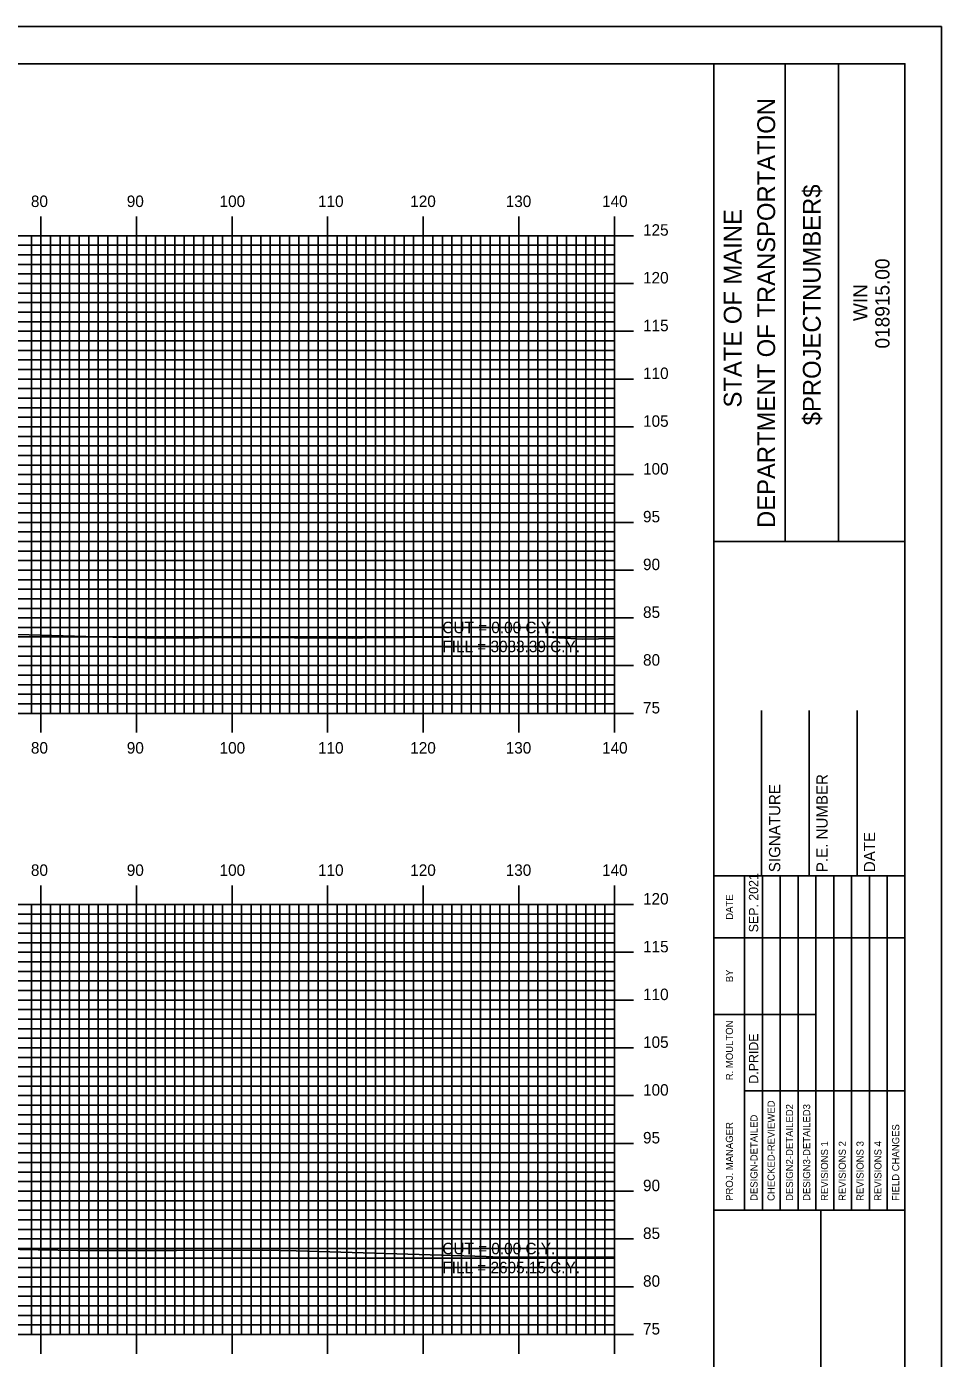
# Model space of a CAD drawing. Extents: x 855690 to 856034, y 364366 to 364586.
# Drawn here: x 855934.8 to 856030.5, y 364446.3 to 364585.7 of the extents above; entities that cross this region are included whole.
import ezdxf

# ---------------------------------------------------------------- set-up
doc = ezdxf.new("R2010")
doc.units = 0
for name, color, linetype in [('BORDER', 7, 'Continuous'), ('D_Text_Standard', 7, 'Continuous'), ('H_V ANNOTATION', 7, 'Continuous'), ('MAJOR', 7, 'Continuous'), ('MINOR', 7, 'Continuous'), ('PLOT BOUNDARY', 7, 'Continuous'), ('S_Roadway_Centerline', 7, 'Continuous')]:
    doc.layers.add(name, color=color, linetype=linetype)

msp = doc.modelspace()

# ---------------------------------------------------------------- linework, layer by layer
at = {"layer": 'BORDER'}
for p, q in [((856006.68, 364371.79), (856006.68, 364581.79)), ((856014.14, 364531.78), (856014.14, 364581.78)), ((856019.73, 364531.78), (856019.73, 364581.78)), ((856006.68, 364531.78), (856026.68, 364531.78)), ((856011.68, 364496.79), (856011.68, 364514.09)), ((856016.68, 364496.79), (856016.68, 364514.09)), ((856021.68, 364496.79), (856021.68, 364514.09)), ((856006.68, 364496.79), (856026.68, 364496.79)), ((856006.68, 364461.79), (856026.68, 364461.79)), ((856017.87, 364391.79), (856017.87, 364461.79))]:
    msp.add_line(p, q, dxfattribs=at)
msp.add_lwpolyline([(855706.68, 364371.79), (856026.68, 364371.79), (856026.68, 364581.79), (855706.68, 364581.79)], close=True, dxfattribs=at)
for points in [[(856009.91, 364490.29), (856009.91, 364496.79)], [(856011.78, 364461.8), (856011.78, 364496.79)], [(856013.64, 364496.79), (856013.64, 364461.8)], [(856015.5, 364461.8), (856015.5, 364496.79)], [(856017.37, 364461.8), (856017.37, 364496.79)], [(856019.23, 364461.8), (856019.23, 364496.79)], [(856021.09, 364461.8), (856021.09, 364496.79)], [(856022.96, 364461.8), (856022.96, 364496.79)], [(856024.82, 364461.8), (856024.82, 364496.79)], [(856009.91, 364461.8), (856009.91, 364495.38)], [(856006.68, 364490.29), (856026.68, 364490.29)], [(856006.68, 364482.29), (856009.91, 364482.29)], [(856009.91, 364482.29), (856017.37, 364482.29)], [(856009.91, 364474.29), (856026.68, 364474.29)]]:
    msp.add_lwpolyline(points, dxfattribs=at)
at = {"layer": 'MAJOR'}
for p, q in [((855936.28, 364565.79), (855936.28, 364563.79)), ((855946.28, 364565.79), (855946.28, 364563.79)), ((855956.28, 364565.79), (855956.28, 364563.79)), ((855966.28, 364565.79), (855966.28, 364563.79)), ((855976.28, 364565.79), (855976.28, 364563.79)), ((855986.28, 364565.79), (855986.28, 364563.79)), ((855996.28, 364565.79), (855996.28, 364563.79)), ((855716.28, 364563.79), (855996.28, 364563.79)), ((855716.28, 364563.79), (855996.28, 364563.79)), ((855936.28, 364513.79), (855936.28, 364563.79)), ((855946.28, 364513.79), (855946.28, 364563.79)), ((855956.28, 364513.79), (855956.28, 364563.79)), ((855966.28, 364513.79), (855966.28, 364563.79)), ((855976.28, 364513.79), (855976.28, 364563.79)), ((855986.28, 364513.79), (855986.28, 364563.79)), ((855998.29, 364563.79), (855994.28, 364563.79)), ((855996.28, 364513.79), (855996.28, 364563.79)), ((855996.28, 364513.79), (855996.28, 364563.79)), ((855716.28, 364558.79), (855996.28, 364558.79)), ((855998.29, 364558.79), (855994.28, 364558.79)), ((855716.28, 364553.79), (855996.28, 364553.79)), ((855998.29, 364553.79), (855994.28, 364553.79)), ((855716.28, 364548.79), (855996.28, 364548.79)), ((855998.29, 364548.79), (855994.28, 364548.79)), ((855716.28, 364543.79), (855996.28, 364543.79)), ((855998.29, 364543.79), (855994.28, 364543.79)), ((855716.28, 364538.79), (855996.28, 364538.79)), ((855998.29, 364538.79), (855994.28, 364538.79)), ((855716.28, 364533.79), (855996.28, 364533.79)), ((855998.29, 364533.79), (855994.28, 364533.79)), ((855716.28, 364528.79), (855996.28, 364528.79)), ((855998.29, 364528.79), (855994.28, 364528.79)), ((855716.28, 364523.79), (855996.28, 364523.79)), ((855998.29, 364523.79), (855994.28, 364523.79)), ((855716.28, 364518.79), (855996.28, 364518.79)), ((855998.29, 364518.79), (855994.28, 364518.79)), ((855716.28, 364513.79), (855996.28, 364513.79)), ((855716.28, 364513.79), (855996.28, 364513.79)), ((855936.28, 364511.78), (855936.28, 364513.79)), ((855946.28, 364511.78), (855946.28, 364513.79)), ((855956.28, 364511.78), (855956.28, 364513.79)), ((855966.28, 364511.78), (855966.28, 364513.79)), ((855976.28, 364511.78), (855976.28, 364513.79)), ((855986.28, 364511.78), (855986.28, 364513.79)), ((855998.29, 364513.79), (855994.28, 364513.79)), ((855996.28, 364511.78), (855996.28, 364513.79)), ((855936.28, 364495.79), (855936.28, 364493.79)), ((855946.28, 364495.79), (855946.28, 364493.79)), ((855956.28, 364495.79), (855956.28, 364493.79)), ((855966.28, 364495.79), (855966.28, 364493.79)), ((855976.28, 364495.79), (855976.28, 364493.79)), ((855986.28, 364495.79), (855986.28, 364493.79)), ((855996.28, 364495.79), (855996.28, 364493.79)), ((855716.28, 364493.79), (855996.28, 364493.79)), ((855716.28, 364493.79), (855996.28, 364493.79)), ((855936.28, 364448.79), (855936.28, 364493.79)), ((855946.28, 364448.79), (855946.28, 364493.79)), ((855956.28, 364448.79), (855956.28, 364493.79)), ((855966.28, 364448.79), (855966.28, 364493.79)), ((855976.28, 364448.79), (855976.28, 364493.79)), ((855986.28, 364448.79), (855986.28, 364493.79)), ((855998.29, 364493.79), (855994.28, 364493.79)), ((855996.28, 364448.79), (855996.28, 364493.79)), ((855996.28, 364448.79), (855996.28, 364493.79)), ((855716.28, 364488.79), (855996.28, 364488.79)), ((855998.29, 364488.79), (855994.28, 364488.79)), ((855716.28, 364483.79), (855996.28, 364483.79)), ((855998.29, 364483.79), (855994.28, 364483.79)), ((855716.28, 364478.79), (855996.28, 364478.79)), ((855998.29, 364478.79), (855994.28, 364478.79)), ((855716.28, 364473.79), (855996.28, 364473.79)), ((855998.29, 364473.79), (855994.28, 364473.79)), ((855716.28, 364468.79), (855996.28, 364468.79)), ((855998.29, 364468.79), (855994.28, 364468.79)), ((855716.28, 364463.79), (855996.28, 364463.79)), ((855998.29, 364463.79), (855994.28, 364463.79)), ((855716.28, 364458.79), (855996.28, 364458.79)), ((855998.29, 364458.79), (855994.28, 364458.79)), ((855716.28, 364453.79), (855996.28, 364453.79)), ((855998.29, 364453.79), (855994.28, 364453.79)), ((855716.28, 364448.79), (855996.28, 364448.79)), ((855716.28, 364448.79), (855996.28, 364448.79)), ((855936.28, 364446.78), (855936.28, 364448.79)), ((855946.28, 364446.78), (855946.28, 364448.79)), ((855956.28, 364446.78), (855956.28, 364448.79)), ((855966.28, 364446.78), (855966.28, 364448.79)), ((855976.28, 364446.78), (855976.28, 364448.79)), ((855986.28, 364446.78), (855986.28, 364448.79)), ((855998.29, 364448.79), (855994.28, 364448.79)), ((855996.28, 364446.78), (855996.28, 364448.79))]:
    msp.add_line(p, q, dxfattribs=at)
at = {"layer": 'MINOR'}
for p, q in [((855716.28, 364562.79), (855996.28, 364562.79)), ((855935.28, 364513.79), (855935.28, 364563.79)), ((855937.28, 364513.79), (855937.28, 364563.79)), ((855938.28, 364513.79), (855938.28, 364563.79)), ((855939.28, 364513.79), (855939.28, 364563.79)), ((855940.28, 364513.79), (855940.28, 364563.79)), ((855941.28, 364513.79), (855941.28, 364563.79)), ((855942.28, 364513.79), (855942.28, 364563.79)), ((855943.28, 364513.79), (855943.28, 364563.79)), ((855944.28, 364513.79), (855944.28, 364563.79)), ((855945.28, 364513.79), (855945.28, 364563.79)), ((855947.28, 364513.79), (855947.28, 364563.79)), ((855948.28, 364513.79), (855948.28, 364563.79)), ((855949.28, 364513.79), (855949.28, 364563.79)), ((855950.28, 364513.79), (855950.28, 364563.79)), ((855951.28, 364513.79), (855951.28, 364563.79)), ((855952.28, 364513.79), (855952.28, 364563.79)), ((855953.28, 364513.79), (855953.28, 364563.79)), ((855954.28, 364513.79), (855954.28, 364563.79)), ((855955.28, 364513.79), (855955.28, 364563.79)), ((855957.28, 364513.79), (855957.28, 364563.79)), ((855958.28, 364513.79), (855958.28, 364563.79)), ((855959.28, 364513.79), (855959.28, 364563.79)), ((855960.28, 364513.79), (855960.28, 364563.79)), ((855961.28, 364513.79), (855961.28, 364563.79)), ((855962.28, 364513.79), (855962.28, 364563.79)), ((855963.28, 364513.79), (855963.28, 364563.79)), ((855964.28, 364513.79), (855964.28, 364563.79)), ((855965.28, 364513.79), (855965.28, 364563.79)), ((855967.28, 364513.79), (855967.28, 364563.79)), ((855968.28, 364513.79), (855968.28, 364563.79)), ((855969.28, 364513.79), (855969.28, 364563.79)), ((855970.28, 364513.79), (855970.28, 364563.79)), ((855971.28, 364513.79), (855971.28, 364563.79)), ((855972.28, 364513.79), (855972.28, 364563.79)), ((855973.28, 364513.79), (855973.28, 364563.79)), ((855974.28, 364513.79), (855974.28, 364563.79)), ((855975.28, 364513.79), (855975.28, 364563.79)), ((855977.28, 364513.79), (855977.28, 364563.79)), ((855978.28, 364513.79), (855978.28, 364563.79)), ((855979.28, 364513.79), (855979.28, 364563.79)), ((855980.28, 364513.79), (855980.28, 364563.79)), ((855981.28, 364513.79), (855981.28, 364563.79)), ((855982.28, 364513.79), (855982.28, 364563.79)), ((855983.28, 364513.79), (855983.28, 364563.79)), ((855984.28, 364513.79), (855984.28, 364563.79)), ((855985.28, 364513.79), (855985.28, 364563.79)), ((855987.28, 364513.79), (855987.28, 364563.79)), ((855988.28, 364513.79), (855988.28, 364563.79)), ((855989.28, 364513.79), (855989.28, 364563.79)), ((855990.28, 364513.79), (855990.28, 364563.79)), ((855991.28, 364513.79), (855991.28, 364563.79)), ((855992.28, 364513.79), (855992.28, 364563.79)), ((855993.28, 364513.79), (855993.28, 364563.79)), ((855994.28, 364513.79), (855994.28, 364563.79)), ((855996.28, 364562.79), (855994.28, 364562.79)), ((855995.28, 364513.79), (855995.28, 364563.79)), ((855716.28, 364561.79), (855996.28, 364561.79)), ((855996.28, 364561.79), (855994.28, 364561.79)), ((855716.28, 364560.79), (855996.28, 364560.79)), ((855996.28, 364560.79), (855994.28, 364560.79)), ((855716.28, 364559.79), (855996.28, 364559.79)), ((855996.28, 364559.79), (855994.28, 364559.79)), ((855716.28, 364557.79), (855996.28, 364557.79)), ((855996.28, 364557.79), (855994.28, 364557.79)), ((855716.28, 364556.79), (855996.28, 364556.79)), ((855716.28, 364555.79), (855996.28, 364555.79)), ((855996.28, 364556.79), (855994.28, 364556.79)), ((855996.28, 364555.79), (855994.28, 364555.79)), ((855716.28, 364554.79), (855996.28, 364554.79)), ((855996.28, 364554.79), (855994.28, 364554.79)), ((855716.28, 364552.79), (855996.28, 364552.79)), ((855716.28, 364551.79), (855996.28, 364551.79)), ((855996.28, 364552.79), (855994.28, 364552.79)), ((855996.28, 364551.79), (855994.28, 364551.79)), ((855716.28, 364550.79), (855996.28, 364550.79)), ((855996.28, 364550.79), (855994.28, 364550.79)), ((855716.28, 364549.79), (855996.28, 364549.79)), ((855996.28, 364549.79), (855994.28, 364549.79)), ((855716.28, 364547.79), (855996.28, 364547.79)), ((855996.28, 364547.79), (855994.28, 364547.79)), ((855716.28, 364546.79), (855996.28, 364546.79)), ((855996.28, 364546.79), (855994.28, 364546.79)), ((855716.28, 364545.79), (855996.28, 364545.79)), ((855716.28, 364544.79), (855996.28, 364544.79)), ((855996.28, 364545.79), (855994.28, 364545.79)), ((855996.28, 364544.79), (855994.28, 364544.79)), ((855716.28, 364542.79), (855996.28, 364542.79)), ((855716.28, 364541.79), (855996.28, 364541.79)), ((855996.28, 364542.79), (855994.28, 364542.79)), ((855996.28, 364541.79), (855994.28, 364541.79)), ((855716.28, 364540.79), (855996.28, 364540.79)), ((855996.28, 364540.79), (855994.28, 364540.79)), ((855716.28, 364539.79), (855996.28, 364539.79)), ((855996.28, 364539.79), (855994.28, 364539.79)), ((855716.28, 364537.79), (855996.28, 364537.79)), ((855996.28, 364537.79), (855994.28, 364537.79)), ((855716.28, 364536.79), (855996.28, 364536.79)), ((855996.28, 364536.79), (855994.28, 364536.79)), ((855716.28, 364535.79), (855996.28, 364535.79)), ((855716.28, 364534.79), (855996.28, 364534.79)), ((855996.28, 364535.79), (855994.28, 364535.79)), ((855996.28, 364534.79), (855994.28, 364534.79)), ((855716.28, 364532.79), (855996.28, 364532.79)), ((855996.28, 364532.79), (855994.28, 364532.79)), ((855716.28, 364531.79), (855996.28, 364531.79)), ((855716.28, 364530.79), (855996.28, 364530.79)), ((855996.28, 364531.79), (855994.28, 364531.79)), ((855996.28, 364530.79), (855994.28, 364530.79)), ((855716.28, 364529.79), (855996.28, 364529.79)), ((855996.28, 364529.79), (855994.28, 364529.79)), ((855716.28, 364527.79), (855996.28, 364527.79)), ((855996.28, 364527.79), (855994.28, 364527.79)), ((855716.28, 364526.79), (855996.28, 364526.79)), ((855996.28, 364526.79), (855994.28, 364526.79)), ((855716.28, 364525.79), (855996.28, 364525.79)), ((855996.28, 364525.79), (855994.28, 364525.79)), ((855716.28, 364524.79), (855996.28, 364524.79)), ((855996.28, 364524.79), (855994.28, 364524.79)), ((855716.28, 364522.79), (855996.28, 364522.79)), ((855996.28, 364522.79), (855994.28, 364522.79)), ((855716.28, 364521.79), (855996.28, 364521.79)), ((855716.28, 364520.79), (855996.28, 364520.79)), ((855996.28, 364521.79), (855994.28, 364521.79)), ((855996.28, 364520.79), (855994.28, 364520.79)), ((855716.28, 364519.79), (855996.28, 364519.79)), ((855996.28, 364519.79), (855994.28, 364519.79)), ((855716.28, 364517.79), (855996.28, 364517.79)), ((855716.28, 364516.79), (855996.28, 364516.79)), ((855996.28, 364517.79), (855994.28, 364517.79)), ((855996.28, 364516.79), (855994.28, 364516.79)), ((855716.28, 364515.79), (855996.28, 364515.79)), ((855996.28, 364515.79), (855994.28, 364515.79)), ((855716.28, 364514.79), (855996.28, 364514.79)), ((855996.28, 364514.79), (855994.28, 364514.79)), ((855935.28, 364448.79), (855935.28, 364493.79)), ((855937.28, 364448.79), (855937.28, 364493.79)), ((855938.28, 364448.79), (855938.28, 364493.79)), ((855939.28, 364448.79), (855939.28, 364493.79)), ((855940.28, 364448.79), (855940.28, 364493.79)), ((855941.28, 364448.79), (855941.28, 364493.79)), ((855942.28, 364448.79), (855942.28, 364493.79)), ((855943.28, 364448.79), (855943.28, 364493.79)), ((855944.28, 364448.79), (855944.28, 364493.79)), ((855945.28, 364448.79), (855945.28, 364493.79)), ((855947.28, 364448.79), (855947.28, 364493.79)), ((855948.28, 364448.79), (855948.28, 364493.79)), ((855949.28, 364448.79), (855949.28, 364493.79)), ((855950.28, 364448.79), (855950.28, 364493.79)), ((855951.28, 364448.79), (855951.28, 364493.79)), ((855952.28, 364448.79), (855952.28, 364493.79)), ((855953.28, 364448.79), (855953.28, 364493.79)), ((855954.28, 364448.79), (855954.28, 364493.79)), ((855955.28, 364448.79), (855955.28, 364493.79)), ((855957.28, 364448.79), (855957.28, 364493.79)), ((855958.28, 364448.79), (855958.28, 364493.79)), ((855959.28, 364448.79), (855959.28, 364493.79)), ((855960.28, 364448.79), (855960.28, 364493.79)), ((855961.28, 364448.79), (855961.28, 364493.79)), ((855962.28, 364448.79), (855962.28, 364493.79)), ((855963.28, 364448.79), (855963.28, 364493.79)), ((855964.28, 364448.79), (855964.28, 364493.79)), ((855965.28, 364448.79), (855965.28, 364493.79)), ((855967.28, 364448.79), (855967.28, 364493.79)), ((855968.28, 364448.79), (855968.28, 364493.79)), ((855969.28, 364448.79), (855969.28, 364493.79)), ((855970.28, 364448.79), (855970.28, 364493.79)), ((855971.28, 364448.79), (855971.28, 364493.79)), ((855972.28, 364448.79), (855972.28, 364493.79)), ((855973.28, 364448.79), (855973.28, 364493.79)), ((855974.28, 364448.79), (855974.28, 364493.79)), ((855975.28, 364448.79), (855975.28, 364493.79)), ((855977.28, 364448.79), (855977.28, 364493.79)), ((855978.28, 364448.79), (855978.28, 364493.79)), ((855979.28, 364448.79), (855979.28, 364493.79)), ((855980.28, 364448.79), (855980.28, 364493.79)), ((855981.28, 364448.79), (855981.28, 364493.79)), ((855982.28, 364448.79), (855982.28, 364493.79)), ((855983.28, 364448.79), (855983.28, 364493.79)), ((855984.28, 364448.79), (855984.28, 364493.79)), ((855985.28, 364448.79), (855985.28, 364493.79)), ((855987.28, 364448.79), (855987.28, 364493.79)), ((855988.28, 364448.79), (855988.28, 364493.79)), ((855989.28, 364448.79), (855989.28, 364493.79)), ((855990.28, 364448.79), (855990.28, 364493.79)), ((855991.28, 364448.79), (855991.28, 364493.79)), ((855992.28, 364448.79), (855992.28, 364493.79)), ((855993.28, 364448.79), (855993.28, 364493.79)), ((855994.28, 364448.79), (855994.28, 364493.79)), ((855995.28, 364448.79), (855995.28, 364493.79)), ((855716.28, 364492.79), (855996.28, 364492.79)), ((855716.28, 364491.79), (855996.28, 364491.79)), ((855996.28, 364492.79), (855994.28, 364492.79)), ((855996.28, 364491.79), (855994.28, 364491.79)), ((855716.28, 364490.79), (855996.28, 364490.79)), ((855996.28, 364490.79), (855994.28, 364490.79)), ((855716.28, 364489.79), (855996.28, 364489.79)), ((855996.28, 364489.79), (855994.28, 364489.79)), ((855716.28, 364487.79), (855996.28, 364487.79)), ((855996.28, 364487.79), (855994.28, 364487.79)), ((855716.28, 364486.79), (855996.28, 364486.79)), ((855996.28, 364486.79), (855994.28, 364486.79)), ((855716.28, 364485.79), (855996.28, 364485.79)), ((855716.28, 364484.79), (855996.28, 364484.79)), ((855996.28, 364485.79), (855994.28, 364485.79)), ((855996.28, 364484.79), (855994.28, 364484.79)), ((855716.28, 364482.79), (855996.28, 364482.79)), ((855716.28, 364481.79), (855996.28, 364481.79)), ((855996.28, 364482.79), (855994.28, 364482.79)), ((855996.28, 364481.79), (855994.28, 364481.79)), ((855716.28, 364480.79), (855996.28, 364480.79)), ((855996.28, 364480.79), (855994.28, 364480.79)), ((855716.28, 364479.79), (855996.28, 364479.79)), ((855996.28, 364479.79), (855994.28, 364479.79)), ((855716.28, 364477.79), (855996.28, 364477.79)), ((855996.28, 364477.79), (855994.28, 364477.79)), ((855716.28, 364476.79), (855996.28, 364476.79)), ((855996.28, 364476.79), (855994.28, 364476.79)), ((855716.28, 364475.79), (855996.28, 364475.79)), ((855716.28, 364474.79), (855996.28, 364474.79)), ((855996.28, 364475.79), (855994.28, 364475.79)), ((855996.28, 364474.79), (855994.28, 364474.79)), ((855716.28, 364472.79), (855996.28, 364472.79)), ((855996.28, 364472.79), (855994.28, 364472.79)), ((855716.28, 364471.79), (855996.28, 364471.79)), ((855716.28, 364470.79), (855996.28, 364470.79)), ((855996.28, 364471.79), (855994.28, 364471.79)), ((855996.28, 364470.79), (855994.28, 364470.79)), ((855716.28, 364469.79), (855996.28, 364469.79)), ((855996.28, 364469.79), (855994.28, 364469.79)), ((855716.28, 364467.79), (855996.28, 364467.79)), ((855716.28, 364466.79), (855996.28, 364466.79)), ((855996.28, 364467.79), (855994.28, 364467.79)), ((855996.28, 364466.79), (855994.28, 364466.79)), ((855716.28, 364465.79), (855996.28, 364465.79)), ((855996.28, 364465.79), (855994.28, 364465.79)), ((855716.28, 364464.79), (855996.28, 364464.79)), ((855996.28, 364464.79), (855994.28, 364464.79)), ((855716.28, 364462.79), (855996.28, 364462.79)), ((855996.28, 364462.79), (855994.28, 364462.79)), ((855716.28, 364461.79), (855996.28, 364461.79)), ((855996.28, 364461.79), (855994.28, 364461.79)), ((855716.28, 364460.79), (855996.28, 364460.79)), ((855716.28, 364459.79), (855996.28, 364459.79)), ((855996.28, 364460.79), (855994.28, 364460.79)), ((855996.28, 364459.79), (855994.28, 364459.79)), ((855716.28, 364457.79), (855996.28, 364457.79)), ((855716.28, 364456.79), (855996.28, 364456.79)), ((855996.28, 364457.79), (855994.28, 364457.79)), ((855996.28, 364456.79), (855994.28, 364456.79)), ((855716.28, 364455.79), (855996.28, 364455.79)), ((855996.28, 364455.79), (855994.28, 364455.79)), ((855716.28, 364454.79), (855996.28, 364454.79)), ((855996.28, 364454.79), (855994.28, 364454.79)), ((855716.28, 364452.79), (855996.28, 364452.79)), ((855996.28, 364452.79), (855994.28, 364452.79)), ((855716.28, 364451.79), (855996.28, 364451.79)), ((855996.28, 364451.79), (855994.28, 364451.79)), ((855716.28, 364450.79), (855996.28, 364450.79)), ((855716.28, 364449.79), (855996.28, 364449.79)), ((855996.28, 364450.79), (855994.28, 364450.79)), ((855996.28, 364449.79), (855994.28, 364449.79))]:
    msp.add_line(p, q, dxfattribs=at)
at = {"layer": 'PLOT BOUNDARY'}
msp.add_lwpolyline([(855690.5, 364365.67), (856030.5, 364365.67), (856030.5, 364585.67), (855690.5, 364585.67)], close=True, dxfattribs=at)
at = {"layer": 'S_Roadway_Centerline'}
for points in [[(855828.74, 364523.2), (855840.05, 364523.23), (855849.05, 364523), (855851.61, 364522.95), (855855.37, 364522.93), (855868.93, 364522.93), (855883.41, 364522.68), (855886.49, 364522.66), (855888.48, 364522.63), (855899.56, 364522.55), (855909.68, 364522.54), (855914.09, 364522.51), (855922.05, 364522.47), (855927.89, 364522.23), (855942.15, 364521.81), (855948.74, 364521.68), (855956.78, 364521.73), (855968.85, 364521.66), (855969.91, 364521.69), (855988.01, 364521.85), (855992.94, 364521.56), (855996.28, 364521.63)], [(855834.03, 364458.61), (855840.8, 364458.61), (855850.27, 364458.57), (855863.32, 364458.38), (855872.58, 364458.34), (855880.54, 364458.24), (855888.03, 364458.11), (855894.6, 364458.01), (855903.62, 364458.18), (855913.2, 364457.99), (855918.83, 364457.95), (855935.98, 364457.64), (855940.15, 364457.6), (855950.47, 364457.57), (855959.46, 364457.61), (855962.97, 364457.56), (855982.86, 364456.94), (855984.28, 364456.9), (855984.41, 364456.89), (855984.55, 364456.89), (855996.28, 364456.91)]]:
    msp.add_lwpolyline(points, dxfattribs=at)

# ---------------------------------------------------------------- texts
at = {"layer": 'BORDER'}
for s, height, p in [('DEPARTMENT OF TRANSPORTATION', 1.8635, (856013.1, 364533.2)), ('$PROJECTNUMBER$', 1.8635, (856017.87, 364543.95)), ('STATE OF MAINE', 1.8635, (856009.59, 364545.81)), ('018915.00', 1.491, (856025.07, 364551.98)), ('WIN', 1.491, (856022.76, 364554.85)), ('P.E. NUMBER', 1.1811, (856018.6, 364497.18)), ('SIGNATURE', 1.181, (856013.64, 364497.18)), ('DATE', 1.181, (856023.57, 364497.18)), ('SEP. 2021', 0.969, (856011.33, 364490.88)), ('DATE', 0.743, (856008.69, 364492.2)), ('BY', 0.743, (856008.69, 364485.66)), ('R. MOULTON', 0.745, (856008.69, 364475.4)), ('D.PRIDE', 0.969, (856011.33, 364475.04)), ('CHECKED-REVIEWED', 0.7455, (856013.05, 364462.77)), ('DESIGN2-DETAILED2', 0.7455, (856014.98, 364462.77)), ('DESIGN3-DETAILED3', 0.7455, (856016.77, 364462.77)), ('PROJ. MANAGER', 0.7455, (856008.69, 364462.77)), ('DESIGN-DETAILED', 0.7455, (856011.26, 364462.77)), ('FIELD CHANGES', 0.7455, (856026.09, 364462.77)), ('REVISIONS 1', 0.7455, (856018.64, 364462.77)), ('REVISIONS 2', 0.7455, (856020.5, 364462.77)), ('REVISIONS 3', 0.7455, (856022.36, 364462.77)), ('REVISIONS 4', 0.7455, (856024.23, 364462.77))]:
    msp.add_text(s, height=height, rotation=90, dxfattribs=at).set_placement(p)
at = {"layer": 'D_Text_Standard'}
for s, p in [('CUT = 0.00 C.Y.', (855978.28, 364522.19)), ('FILL = 3033.39 C.Y.', (855978.28, 364520.2)), ('CUT = 0.00 C.Y.', (855978.28, 364457.19)), ('FILL = 2605.15 C.Y.', (855978.28, 364455.2))]:
    msp.add_text(s, height=1.2, dxfattribs=at).set_placement(p)
at = {"layer": 'H_V ANNOTATION'}
for s, p in [('80', (855935.23, 364566.79)), ('90', (855945.26, 364566.79)), ('100', (855954.97, 364566.79)), ('110', (855965.27, 364566.79)), ('120', (855974.92, 364566.79)), ('130', (855984.91, 364566.79)), ('140', (855994.99, 364566.79)), ('125', (855999.28, 364563.79)), ('120', (855999.28, 364558.79)), ('115', (855999.28, 364553.79)), ('110', (855999.28, 364548.79)), ('105', (855999.28, 364543.79)), ('100', (855999.28, 364538.79)), ('95', (855999.28, 364533.79)), ('90', (855999.28, 364528.79)), ('85', (855999.28, 364523.79)), ('80', (855999.28, 364518.79)), ('75', (855999.28, 364513.79)), ('80', (855935.23, 364509.59)), ('90', (855945.26, 364509.59)), ('100', (855954.97, 364509.59)), ('110', (855965.27, 364509.59)), ('120', (855974.92, 364509.59)), ('130', (855984.91, 364509.59)), ('140', (855994.99, 364509.59)), ('80', (855935.23, 364496.79)), ('90', (855945.26, 364496.79)), ('100', (855954.97, 364496.79)), ('110', (855965.27, 364496.79)), ('120', (855974.92, 364496.79)), ('130', (855984.91, 364496.79)), ('140', (855994.99, 364496.79)), ('120', (855999.28, 364493.79)), ('115', (855999.28, 364488.79)), ('110', (855999.28, 364483.79)), ('105', (855999.28, 364478.79)), ('100', (855999.28, 364473.79)), ('95', (855999.28, 364468.79)), ('90', (855999.28, 364463.79)), ('85', (855999.28, 364458.79)), ('80', (855999.28, 364453.79)), ('75', (855999.28, 364448.79))]:
    msp.add_text(s, height=1.2, dxfattribs=at).set_placement(p)

doc.saveas('drawing.dxf')
